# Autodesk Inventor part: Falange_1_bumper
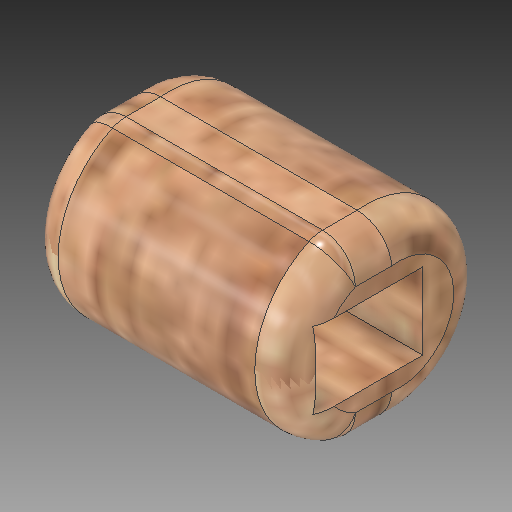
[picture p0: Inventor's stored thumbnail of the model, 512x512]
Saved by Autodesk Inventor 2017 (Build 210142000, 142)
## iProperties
Created: 2017-05
Part Number: Falange_1_bumper
Material: Generic
Document SubType Name: Modeling
Designer: alez_
Density: 1 g/cm^3
Appearance: Birch - Natural Polished
Author: alez_
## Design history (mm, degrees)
sketch "Sketch1"
  geometry: L1 (0, 0)-(24, 0); L2 (0, 0)-(0, -16); L3 (0, -16)-(24, -16); L4 (24, -16)-(24, 0)
  constraints: 8 end point, 2 perpendicular, 1 horizontal, 1 vertical
  dimensions: "d0" = 24 distance of L1.start L1.end; "d1" = 16 distance of L1.start L2.end
extrude "Extrusion1" new body sketch "Sketch1" distance "d2" = 12; taper "d3" = 0 deg
sketch "Sketch2"
  geometry: L1 (16, 0)-(14, 0); L2 (0, 0)-(16, 0) reference; L3 (14, 0)-(14, 2.5); L4 (14, 2.5)-(14, 9.5); L5 (14, 9.5)-(4.25, 9.5); L6 (0, 0)-(0, 12) reference; L7 (4.25, 9.5)-(4.25, 2.5); L8 (4.25, 2.5)-(14, 2.5)
  constraints: 12 end point, 3 perpendicular, 2 point on line, 1 parallel
  dimensions: "d4" = 2 distance of L1.start L1.end; "d5" = 2.5 distance of L1.end L3.end; "d6" = 7 distance of L3.end L4.end; "d7" = 9.75 distance of L4.end L5.end
extrude "Extrusion2" cut sketch "Sketch2" distance "d8" = 24; taper "d9" = 0 deg
sketch "Sketch3"
  geometry: L1 (0, 9.75)-(24, 9.75) reference; L2 (0, 0)-(24, 0) reference; L3 (12, 0)-(12, 4.875); C1 r 3.25 at (12, 4.875); 1 further point
  constraints: 2 end point, 1 centre point, 1 midpoint, 1 vertical
  dimensions: "d12" = 6.5 diameter of C1; "d21" = 4.875 distance of L3.start L3.end
extrude "Extrusion3" join sketch "Sketch3" distance "d13" = 1.5; taper "d14" = 0 deg
sketch "Sketch4"
  geometry: L1 (0, 0)-(24, 0) reference; L2 (0, 9.75)-(24, 9.75) reference; L3 (12, 9.75)-(12, 4.875); C1 r 3.25 at (12, 4.875); 1 further point
  constraints: 2 end point, 1 centre point, 1 midpoint, 1 vertical
  dimensions: "d16" = 6.5 diameter of C1; "d22" = 4.875 distance of L3.start L3.end
extrude "Extrusion4" join sketch "Sketch4" distance "d17" = 1.5; taper "d18" = 0 deg
fillet "Fillet2" dims "d19" = 6
fillet "Fillet3" dims "d20" = 6
fillet "Fillet4" dims "d23" = 2
sketch "Sketch5" dims "d19" = 6
  geometry: L1 (0, 0)-(0, 7) reference; L2 (0, 0)-(9.75, 0); L3 (0, 0)-(0, 7); L4 (0, 7)-(7.686, 7) reference; L5 (0, 7)-(9.75, 7); L6 (9.75, 7)-(9.75, 0); L7 (7.686, 0)-(0, 0) reference; L8 (0, 0)-(3, 0); L9 (8.125, 7)-(1.625, 7) reference; L10 (9.75, 0)-(6.75, 0); L11 (1.625, 0)-(8.125, 0) reference; L12 (3, -4.5)-(6.75, -4.5); L13 (3, 11.5)-(6.75, 11.5); A1 r 8.04 centre (2.197, 3.5) between (3, 11.5) and (3, -4.5); A2 r 8.5 centre (3.878, 3.5) between (6.75, -4.5) and (6.75, 11.5); 1 further point
  constraints: 16 end point, 4 point on circle, 2 centre point, 2 point on line, 2 vertical, 1 collinear, 1 horizontal, 1 parallel
  dimensions: "d24" = 3 distance of L1.start L8.end; "d25" = 4.5 distance of L8.end L12.start; "d27" = 8.04018 radius of A1; "d28" = 3 distance of L2.end L10.end; "d30" = 8.5 radius of A2
extrude "Extrusion5" join sketch "Sketch5" distance "d31" = 24; taper "d32" = 0 deg
fillet "Fillet5" dims "d33" = 3
fillet "Fillet6" dims "d34" = 3
body "Solid1"
